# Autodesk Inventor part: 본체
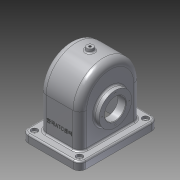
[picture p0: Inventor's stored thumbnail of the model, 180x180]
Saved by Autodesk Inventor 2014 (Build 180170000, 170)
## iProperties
Created: 2016-10
Part Number: 본체
Material: 알루미늄 6061
Document SubType Name: Modeling
Designer: user
Density: 2.71 g/cm^3
Appearance: 알루미늄 - 평지
Mass: 1165.05 g
Surface Area: 1200.06 cm^2
Volume: 429.908 cm^3
Author: user
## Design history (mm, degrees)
sketch "스케치1"
  geometry: L1 (-55, -75)-(55, -75); L2 (55, -75)-(55, 75); L3 (55, 75)-(-55, 75); L4 (-55, 75)-(-55, -75); L5 (-55, -75)-(55, 75); L6 (55, -75)-(-55, 75); 1 further point
  constraints: 12 end point, 2 midpoint, 2 parallel, 1 horizontal, 1 perpendicular
  dimensions: "d0" = 110 distance of L3.end L2.end; "d1" = 150 distance of L2.end L1.end
extrude "돌출1" new body sketch "스케치1" distance "d2" = 15; taper "d3" = 0 deg
fillet "모깎기1" dims "d4" = 12
sketch "스케치2"
  geometry: L1 (0, 0)-(0, 80); L2 (-63, 15)-(63, 15) reference; L3 (-58, 80)-(-58, 15); L4 (58, 80)-(58, 15); A1 r 58 centre (0, 80) between (58, 80) and (-58, 80)
  constraints: 6 end point, 2 perpendicular, 2 point on circle, 2 point on line, 2 tangent, 1 centre point, 1 vertical
  dimensions: "d5" = 80 distance of L1.start L1.end; "d7" = 58 radius of A1
extrude "돌출2" join sketch "스케치2" stored distance "d8" = 77; taper "d9" = 0 deg
sketch "스케치3"
  geometry: L1 (0, 0)-(0, 80); L2 (52, 80)-(52, 0); L3 (-52, 80)-(-52, 0); A1 r 52 centre (0, 80) between (52, 80) and (-52, 80)
  constraints: 6 end point, 2 parallel, 2 point on circle, 2 tangent, 1 centre point, 1 coincident, 1 vertical
  dimensions: "d10" = 80 distance of L1.start L1.end; "d11" = 52 radius of A1
extrude "돌출3" cut sketch "스케치3" stored distance "d13" = 67; taper "d14" = 0 deg
node "작업 평면1"
sketch "스케치4"
  geometry: C1 r 6 at (0, 0); 1 further point
  constraints: 1 centre point, 1 coincident
  dimensions: "d17" = 12 diameter of C1
extrude "돌출4" join sketch "스케치4" stored distance "d18" = 67; taper "d19" = 10 deg
hole "구멍1" diameter "d22" = 4.459; stored, may be unused: countersink angle "d26" = 90 deg, drill point angle "d28" = 0 deg; dims "d23" = 6, "d24" = 4, "d25" = 2, "d27" = 8, "d122" = 10, "d123" = 10
sketch "스케치5"
  geometry: L1 (0, 63)-(0, -63) reference; C1 r 37.5 at (65, 0); A1 r 58 centre (80, 0) between (80, -58) and (80, 58) reference; 1 further point
  constraints: 1 centre point, 1 horizontal alignment
  dimensions: "d86" = 65 distance from line of C1.centre L1; "d87" = 75 diameter of C1
extrude "돌출5" join sketch "스케치5" distance "d31" = 5; taper "d32" = 0 deg
fillet "모깎기2" dims "d66" = 3
fillet "모깎기4" dims "d68" = 13
sketch "스케치10"
  geometry: L1 (-17.5, -80)-(68.5, -80) reference; L2 (-13, 0)-(-13, -65) reference; 2 further points
  constraints: 1 other
  dimensions: "d69" = 40 distance from line of point (25.5, -40) L1; "d71" = 38.5 distance from line of point (25.5, -40) L2
feature "엠보싱1" sketch "스케치10" dims "d0" = 110, "d1" = 150, "d72" = 0.5, "d73" = 0
sketch "스케치11"
  geometry: A1 r 9 centre (-43, -63) between (-52, -63) and (-43, -72) reference; A2 r 9 centre (43, -63) between (43, -72) and (52, -63) reference; A3 r 9 centre (43, 63) between (52, 63) and (43, 72) reference; A4 r 9 centre (-43, 63) between (-43, 72) and (-52, 63) reference; 5 further points
  constraints: 4 coincident
hole "구멍5" sketch "스케치11" at (-43, 63), (43, 63), (43, -63), (-43, -63) diameter "d74" = 5; stored, may be unused: countersink angle "d78" = 90 deg, drill point angle "d80" = 0 deg; dims "d75" = 6, "d76" = 12, "d77" = 5, "d79" = 8
fillet "모깎기5" dims "d81" = 3
fillet "모깎기6" dims "d85" = 8
sketch "스케치12"
  geometry: L1 (0, -63)-(0, 63) reference; C1 r 31 at (-65, 0); A1 r 45 centre (-80, 0) between (-80, 45) and (-80, -45) reference; 1 further point
  constraints: 1 centre point, 1 horizontal alignment
  dimensions: "d88" = 62 diameter of C1; "d89" = 65 distance from line of C1.centre L1
extrude "돌출8" join sketch "스케치12" distance "d90" = 10; taper "d91" = 0 deg
fillet "모깎기7" dims "d92" = 3
sketch "스케치13"
  geometry: C1 r 37.5 at (0, 0) reference; A1 r 29 centre (0, 0) between (0, 29) and (29, 0); 3 further points
  constraints: 4 point on circle, 1 centre point, 1 coincident
  dimensions: "d93" = 58 diameter of A1
hole "구멍6" sketch "스케치13" at (0, 29), (29, 0), (0, -29), (-29, 0) diameter "d94" = 2.459; stored, may be unused: countersink angle "d98" = 90 deg, drill point angle "d100" = 118 deg; dims "d95" = 6, "d96" = 4, "d97" = 2, "d99" = 8
sketch "스케치14"
  geometry: C1 r 31 at (0, 0) reference; A1 r 26 centre (0, 0) between (0, 26) and (26, 0); 3 further points
  constraints: 4 point on circle, 1 centre point, 1 coincident
  dimensions: "d101" = 52 diameter of A1
hole "구멍7" sketch "스케치14" at (0, 26), (26, 0), (0, -26), (-26, 0) diameter "d102" = 2.459; stored, may be unused: countersink angle "d106" = 90 deg, drill point angle "d108" = 118 deg; dims "d103" = 6, "d104" = 4, "d105" = 2, "d107" = 8
sketch "스케치15"
  geometry: C1 r 37.5 at (0, 0) reference; C2 r 20 at (0, 0); 1 further point
  constraints: 1 centre point, 1 coincident
  dimensions: "d109" = 40 diameter of C2
extrude "돌출9" cut sketch "스케치15" distance "d110" = 24; taper "d111" = 0 deg
sketch "스케치16"
  geometry: C1 r 31 at (0, 0) reference; C2 r 20 at (0, 0); 1 further point
  constraints: 1 centre point, 1 coincident
  dimensions: "d112" = 40 diameter of C2
extrude "돌출10" cut sketch "스케치16" distance "d113" = 15; taper "d114" = 0 deg
chamfer "모따기2" distance "d115" = 1; stored, may be unused: second distance "d116" = 2, angle "d117" = 45 deg
node "작업 평면2"
sketch "스케치19"
  geometry: C1 r 28 at (0, 0); 1 further point
  constraints: 1 centre point
  dimensions: "d121" = 56 diameter of C1
extrude "돌출11" join sketch "스케치19" distance "d124" = 15; taper "d125" = 40 deg
sketch "스케치20"
  geometry: C1 r 21 at (0, 0) reference; C2 r 20 at (0, 0); 1 further point
  constraints: 1 centre point, 1 coincident
  dimensions: "d126" = 40 diameter of C2
extrude "돌출12" cut sketch "스케치20" distance "d127" = 24; taper "d128" = 0 deg
node "솔리드1"
other parameters: "d12" = 67, "d15" = -144, "d120" = -24
